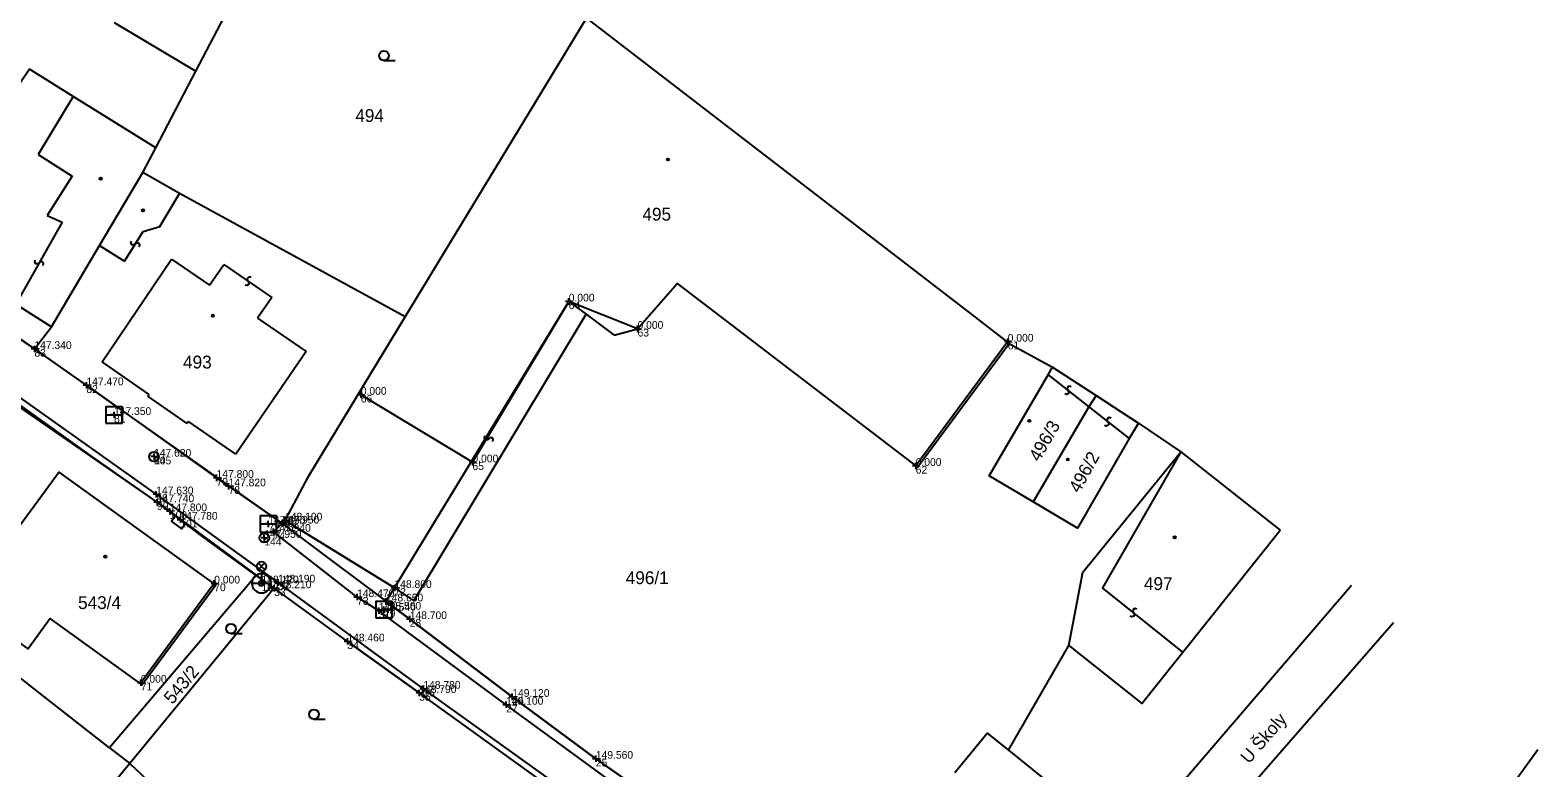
# Model space of a CAD drawing. Extents: x -748509 to -748117, y -967868 to -967533.
# Drawn here: x -748249.3 to -748131.8, y -967661.4 to -967603.9 of the extents above; entities that cross this region are included whole.
import ezdxf

# ---------------------------------------------------------------- set-up
doc = ezdxf.new("R2010")
doc.units = 0
for name, color, linetype in [('Body polohopisu', 7, 'Continuous'), ('Budovy', 7, 'Continuous'), ('Doplňkové značky', 7, 'Continuous'), ('KM', 7, 'Continuous'), ('Ploty_opěrné zdi', 7, 'Continuous'), ('Rozhraní ploch', 7, 'Continuous'), ('Vnitřní kresba', 7, 'Continuous'), ('Vstup na pozemek', 7, 'Continuous'), ('Výšky bodů', 7, 'Continuous'), ('Značky IS', 7, 'Continuous'), ('Čísla bodů', 7, 'Continuous')]:
    doc.layers.add(name, color=color, linetype=linetype)

msp = doc.modelspace()

# ---------------------------------------------------------------- linework, layer by layer
at = {"layer": 'Body polohopisu'}
for p, q in [((-748207.35, -967625.04), (-748207.6, -967625.04)), ((-748207.35, -967625.04), (-748207.35, -967624.79)), ((-748207.35, -967625.04), (-748207.1, -967625.04)), ((-748207.35, -967625.04), (-748207.35, -967625.29)), ((-748201.99, -967627.17), (-748202.24, -967627.17)), ((-748201.99, -967627.17), (-748201.99, -967626.92)), ((-748201.99, -967627.17), (-748201.74, -967627.17)), ((-748201.99, -967627.17), (-748201.99, -967627.42)), ((-748248.98, -967628.74), (-748249.23, -967628.74)), ((-748248.98, -967628.74), (-748248.98, -967628.49)), ((-748248.98, -967628.74), (-748248.73, -967628.74)), ((-748248.98, -967628.74), (-748248.98, -967628.99)), ((-748173.15, -967628.17), (-748173.4, -967628.17)), ((-748173.15, -967628.17), (-748173.15, -967627.92)), ((-748173.15, -967628.17), (-748172.9, -967628.17)), ((-748173.15, -967628.17), (-748173.15, -967628.42)), ((-748244.93, -967631.57), (-748245.18, -967631.57)), ((-748244.93, -967631.57), (-748244.93, -967631.32)), ((-748244.93, -967631.57), (-748244.68, -967631.57)), ((-748244.93, -967631.57), (-748244.93, -967631.82)), ((-748223.55, -967632.31), (-748223.8, -967632.31)), ((-748223.55, -967632.31), (-748223.55, -967632.06)), ((-748223.55, -967632.31), (-748223.3, -967632.31)), ((-748223.55, -967632.31), (-748223.55, -967632.56)), ((-748242.78, -967633.88), (-748243.03, -967633.88)), ((-748242.78, -967633.88), (-748242.78, -967633.63)), ((-748242.78, -967633.88), (-748242.53, -967633.88)), ((-748242.78, -967633.88), (-748242.78, -967634.13)), ((-748239.66, -967637.13), (-748239.66, -967636.88)), ((-748239.66, -967637.13), (-748239.66, -967636.88)), ((-748239.66, -967637.13), (-748239.91, -967637.13)), ((-748239.66, -967637.13), (-748239.91, -967637.13)), ((-748239.66, -967637.13), (-748239.41, -967637.13)), ((-748239.66, -967637.13), (-748239.66, -967637.38)), ((-748239.66, -967637.13), (-748239.41, -967637.13)), ((-748239.66, -967637.13), (-748239.66, -967637.38)), ((-748214.85, -967637.57), (-748215.1, -967637.57)), ((-748214.85, -967637.57), (-748214.85, -967637.32)), ((-748214.85, -967637.57), (-748214.6, -967637.57)), ((-748214.85, -967637.57), (-748214.85, -967637.82)), ((-748180.32, -967637.85), (-748180.57, -967637.85)), ((-748180.32, -967637.85), (-748180.32, -967637.6)), ((-748180.32, -967637.85), (-748180.07, -967637.85)), ((-748180.32, -967637.85), (-748180.32, -967638.1)), ((-748234.79, -967638.78), (-748235.04, -967638.78)), ((-748234.79, -967638.78), (-748234.79, -967638.53)), ((-748234.79, -967638.78), (-748234.54, -967638.78)), ((-748234.79, -967638.78), (-748234.79, -967639.03)), ((-748233.85, -967639.44), (-748233.85, -967639.19)), ((-748239.49, -967640.06), (-748239.74, -967640.06)), ((-748239.49, -967640.06), (-748239.49, -967639.81)), ((-748239.49, -967640.06), (-748239.24, -967640.06)), ((-748239.49, -967640.06), (-748239.49, -967640.31)), ((-748239.43, -967640.68), (-748239.43, -967640.43)), ((-748233.85, -967639.44), (-748234.1, -967639.44)), ((-748233.85, -967639.44), (-748233.6, -967639.44)), ((-748233.85, -967639.44), (-748233.85, -967639.69)), ((-748239.43, -967640.68), (-748239.68, -967640.68)), ((-748239.43, -967640.68), (-748239.18, -967640.68)), ((-748239.43, -967640.68), (-748239.43, -967640.93)), ((-748238.43, -967641.38), (-748238.68, -967641.38)), ((-748238.43, -967641.38), (-748238.43, -967641.13)), ((-748238.43, -967641.38), (-748238.18, -967641.38)), ((-748238.43, -967641.38), (-748238.43, -967641.63)), ((-748237.61, -967642.04), (-748237.86, -967642.04)), ((-748237.61, -967642.04), (-748237.61, -967641.79)), ((-748237.61, -967642.04), (-748237.36, -967642.04)), ((-748237.61, -967642.04), (-748237.61, -967642.29)), ((-748230.76, -967642.37), (-748231.01, -967642.37)), ((-748230.76, -967642.37), (-748230.76, -967642.12)), ((-748230.76, -967642.37), (-748230.51, -967642.37)), ((-748230.76, -967642.37), (-748230.76, -967642.62)), ((-748230.35, -967642.98), (-748230.35, -967642.73)), ((-748229.69, -967642.34), (-748229.94, -967642.34)), ((-748229.45, -967642.1), (-748229.7, -967642.1)), ((-748229.69, -967642.34), (-748229.69, -967642.09)), ((-748229.69, -967642.34), (-748229.44, -967642.34)), ((-748229.69, -967642.34), (-748229.69, -967642.59)), ((-748229.45, -967642.1), (-748229.45, -967641.85)), ((-748229.45, -967642.1), (-748229.2, -967642.1)), ((-748229.45, -967642.1), (-748229.45, -967642.35)), ((-748231.07, -967643.45), (-748231.32, -967643.45)), ((-748231.07, -967643.45), (-748231.07, -967643.2)), ((-748231.07, -967643.45), (-748230.82, -967643.45)), ((-748231.07, -967643.45), (-748231.07, -967643.7)), ((-748230.35, -967642.98), (-748230.6, -967642.98)), ((-748230.35, -967642.98), (-748230.1, -967642.98)), ((-748230.35, -967642.98), (-748230.35, -967643.23)), ((-748234.97, -967647.01), (-748235.22, -967647.01)), ((-748234.97, -967647.01), (-748234.97, -967646.76)), ((-748234.97, -967647.01), (-748234.72, -967647.01)), ((-748234.97, -967647.01), (-748234.97, -967647.26)), ((-748231.29, -967647), (-748231.54, -967647)), ((-748231.29, -967647), (-748231.29, -967646.75)), ((-748231.29, -967647), (-748231.04, -967647)), ((-748231.29, -967647), (-748231.29, -967647.25)), ((-748230.3, -967647.38), (-748230.55, -967647.38)), ((-748230.3, -967647.38), (-748230.3, -967647.13)), ((-748230.3, -967647.38), (-748230.05, -967647.38)), ((-748230.3, -967647.38), (-748230.3, -967647.63)), ((-748230, -967646.93), (-748230.25, -967646.93)), ((-748230, -967646.93), (-748230, -967646.68)), ((-748230, -967646.93), (-748229.75, -967646.93)), ((-748230, -967646.93), (-748230, -967647.18)), ((-748220.93, -967647.36), (-748221.18, -967647.36)), ((-748220.93, -967647.36), (-748220.93, -967647.11)), ((-748220.93, -967647.36), (-748220.68, -967647.36)), ((-748220.93, -967647.36), (-748220.93, -967647.61)), ((-748223.84, -967648.07), (-748224.09, -967648.07)), ((-748223.84, -967648.07), (-748223.84, -967647.82)), ((-748223.84, -967648.07), (-748223.59, -967648.07)), ((-748223.84, -967648.07), (-748223.84, -967648.32)), ((-748221.59, -967648.41), (-748221.84, -967648.41)), ((-748221.75, -967649.05), (-748221.75, -967648.8)), ((-748221.59, -967648.41), (-748221.59, -967648.16)), ((-748221.59, -967648.41), (-748221.34, -967648.41)), ((-748221.59, -967648.41), (-748221.59, -967648.66)), ((-748222.16, -967649.13), (-748222.41, -967649.13)), ((-748222.16, -967649.13), (-748222.16, -967648.88)), ((-748222.16, -967649.13), (-748221.91, -967649.13)), ((-748222.16, -967649.13), (-748222.16, -967649.38)), ((-748221.75, -967649.05), (-748222, -967649.05)), ((-748221.75, -967649.05), (-748221.5, -967649.05)), ((-748221.75, -967649.05), (-748221.75, -967649.3)), ((-748219.74, -967649.78), (-748219.99, -967649.78)), ((-748219.74, -967649.78), (-748219.74, -967649.53)), ((-748219.74, -967649.78), (-748219.49, -967649.78)), ((-748219.74, -967649.78), (-748219.74, -967650.03)), ((-748224.6, -967651.52), (-748224.85, -967651.52)), ((-748224.6, -967651.52), (-748224.6, -967651.27)), ((-748224.6, -967651.52), (-748224.35, -967651.52)), ((-748224.6, -967651.52), (-748224.6, -967651.77)), ((-748240.69, -967654.74), (-748240.69, -967654.49)), ((-748240.69, -967654.74), (-748240.94, -967654.74)), ((-748240.69, -967654.74), (-748240.44, -967654.74)), ((-748240.69, -967654.74), (-748240.69, -967654.99)), ((-748219, -967655.54), (-748219.25, -967655.54)), ((-748219, -967655.54), (-748219, -967655.29)), ((-748219, -967655.54), (-748218.75, -967655.54)), ((-748219, -967655.54), (-748219, -967655.79)), ((-748218.68, -967655.21), (-748218.93, -967655.21)), ((-748218.68, -967655.21), (-748218.68, -967654.96)), ((-748218.68, -967655.21), (-748218.43, -967655.21)), ((-748218.68, -967655.21), (-748218.68, -967655.46)), ((-748211.75, -967655.84), (-748212, -967655.84)), ((-748211.75, -967655.84), (-748211.75, -967655.59)), ((-748211.75, -967655.84), (-748211.5, -967655.84)), ((-748211.75, -967655.84), (-748211.75, -967656.09)), ((-748212.23, -967656.45), (-748212.48, -967656.45)), ((-748212.23, -967656.45), (-748212.23, -967656.2)), ((-748212.23, -967656.45), (-748211.98, -967656.45)), ((-748212.23, -967656.45), (-748212.23, -967656.7)), ((-748205.24, -967660.66), (-748205.24, -967660.41)), ((-748205.24, -967660.66), (-748205.49, -967660.66)), ((-748205.24, -967660.66), (-748204.99, -967660.66)), ((-748205.24, -967660.66), (-748205.24, -967660.91))]:
    msp.add_line(p, q, dxfattribs=at)
at = {"layer": 'Budovy'}
for points in [[(-748201.99, -967627.17), (-748207.35, -967625.04), (-748214.85, -967637.57), (-748223.55, -967632.31)], [(-748173.15, -967628.17), (-748180.32, -967637.85)], [(-748220.93, -967647.36), (-748229.45, -967642.1)], [(-748234.97, -967647.01), (-748240.69, -967654.74)]]:
    msp.add_lwpolyline(points, dxfattribs=at)
at = {"layer": 'Doplňkové značky'}
for p, q in [((-748231.55, -967645.94), (-748231.03, -967645.41)), ((-748231.02, -967645.94), (-748231.55, -967645.41)), ((-748231.29, -967646.05), (-748231.29, -967646.8))]:
    msp.add_line(p, q, dxfattribs=at)
for centre, radius in [((-748231.29, -967645.68), 0.375), ((-748231.29, -967647), 0.2)]:
    msp.add_circle(centre, radius, dxfattribs=at)
at = {"layer": 'KM'}
for p, q in [((-748236.4, -967607.09), (-748226.27, -967587.7)), ((-748220.09, -967626.24), (-748205.97, -967602.97)), ((-748242.78, -967603.32), (-748236.4, -967607.09)), ((-748221.75, -967606.28), (-748220.87, -967606.28)), ((-748239.53, -967613.07), (-748236.4, -967607.09)), ((-748240.54, -967615), (-748239.53, -967613.07)), ((-748259.38, -967621.54), (-748248.98, -967628.74)), ((-748248.98, -967628.74), (-748229.69, -967642.34)), ((-748173.05, -967628.31), (-748169.65, -967630.17)), ((-748169.65, -967630.17), (-748166.27, -967632.36)), ((-748166.27, -967632.36), (-748162.97, -967634.53)), ((-748162.97, -967634.53), (-748159.66, -967636.76)), ((-748159.66, -967636.76), (-748151.92, -967642.86)), ((-748229.69, -967642.34), (-748229.45, -967642.1)), ((-748231.71, -967646.39), (-748243.13, -967659.81)), ((-748230.3, -967647.38), (-748231.71, -967646.39)), ((-748230.3, -967647.38), (-748241.55, -967661.04)), ((-748163.76, -967667.39), (-748146.37, -967647.14)), ((-748233.67, -967650.91), (-748232.79, -967650.91)), ((-748173.09, -967660), (-748168.38, -967651.84)), ((-748227.2, -967657.58), (-748226.32, -967657.58)), ((-748243.13, -967659.81), (-748241.55, -967661.04)), ((-748159.06, -967697.45), (-748131.85, -967659.94)), ((-748241.55, -967661.04), (-748256.12, -967678.46)), ((-748241.55, -967661.04), (-748221.23, -967680.08))]:
    msp.add_line(p, q, dxfattribs=at)
for points in [[(-748205.97, -967602.97), (-748176.02, -967626), (-748173.05, -967628.31)], [(-748239.53, -967613.07), (-748245.95, -967609.07), (-748249.36, -967606.94), (-748251.89, -967610.64), (-748259.47, -967605.44), (-748265.77, -967614.58), (-748258.33, -967619.66), (-748259.38, -967621.54)], [(-748248.98, -967628.74), (-748247.66, -967627.02), (-748243.91, -967620.68), (-748240.54, -967615)], [(-748220.09, -967626.24), (-748237.67, -967616.64), (-748240.54, -967615)], [(-748231.71, -967646.39), (-748235.78, -967643.43), (-748239.43, -967640.68), (-748244.42, -967637.16), (-748269.93, -967618.95)], [(-748229.45, -967642.1), (-748220.93, -967647.36), (-748219.41, -967648.37), (-748206, -967626.04), (-748203.81, -967627.67), (-748201.99, -967627.17), (-748198.9, -967623.64), (-748196.5, -967625.48), (-748180.19, -967637.95), (-748173.05, -967628.31)], [(-748229.45, -967642.1), (-748227.6, -967638.63), (-748220.09, -967626.24)], [(-748171.16, -967640.65), (-748174.6, -967638.62), (-748170, -967630.75), (-748169.65, -967630.17)], [(-748166.27, -967632.36), (-748166.83, -967633.25), (-748171.16, -967640.65)], [(-748162.97, -967634.53), (-748163.69, -967635.72), (-748167.71, -967642.69), (-748171.16, -967640.65)], [(-748168.38, -967651.84), (-748167.3, -967646.13), (-748159.66, -967636.76)], [(-748254.51, -967648.43), (-748247.07, -967638.35), (-748234.85, -967647.14), (-748240.58, -967654.9), (-748247.76, -967649.74), (-748249.46, -967652.1), (-748254.51, -967648.43)], [(-748229.69, -967642.34), (-748219.74, -967649.78), (-748211.75, -967655.84), (-748205.24, -967660.66), (-748198.43, -967665.43), (-748187.84, -967672.99), (-748185.42, -967672.41), (-748179.89, -967671.41), (-748179.35, -967670.75)], [(-748168.38, -967651.84), (-748162.71, -967656.37), (-748159.5, -967652.36), (-748151.92, -967642.86)], [(-748208.42, -967663.17), (-748219, -967655.54), (-748224.6, -967651.52), (-748230.3, -967647.38)], [(-748243.13, -967659.81), (-748248.64, -967655.5), (-748256.43, -967649.41)], [(-748143.1, -967650.08), (-748174.48, -967686.04), (-748161.31, -967696.92), (-748159.06, -967697.45)], [(-748177.27, -967661.74), (-748174.74, -967658.67), (-748173.09, -967660)], [(-748173.09, -967660), (-748168.63, -967663.6), (-748163.76, -967667.39)]]:
    msp.add_lwpolyline(points, dxfattribs=at)
for centre, radius in [((-748221.75, -967605.9), 0.375), ((-748199.62, -967613.98), 0.0875), ((-748243.82, -967615.47), 0.0875), ((-748240.53, -967617.94), 0.0875), ((-748235.08, -967626.15), 0.0875), ((-748171.46, -967634.34), 0.0875), ((-748168.47, -967637.35), 0.0875), ((-748160.14, -967643.42), 0.0875), ((-748243.45, -967644.92), 0.0875), ((-748233.67, -967650.53), 0.375), ((-748227.2, -967657.2), 0.375)]:
    msp.add_circle(centre, radius, dxfattribs=at)
at = {"layer": 'Ploty_opěrné zdi'}
for points in [[(-748239.43, -967640.68), (-748254.08, -967630.54), (-748266.63, -967622)], [(-748248.98, -967628.74), (-748255.39, -967624.4)], [(-748244.93, -967631.57), (-748234.79, -967638.78)], [(-748233.85, -967639.44), (-748229.69, -967642.34)], [(-748224.6, -967651.52), (-748230.3, -967647.38), (-748238.43, -967641.38)], [(-748219.74, -967649.78), (-748221.59, -967648.41), (-748220.93, -967647.36)], [(-748211.75, -967655.84), (-748219.74, -967649.78)], [(-748199.23, -967672.68), (-748197.92, -967671.02), (-748208.42, -967663.17), (-748219, -967655.54)], [(-748188.75, -967672.34), (-748198.43, -967665.43), (-748205.24, -967660.66), (-748211.75, -967655.84)]]:
    msp.add_lwpolyline(points, dxfattribs=at)
at = {"layer": 'Rozhraní ploch'}
for points in [[(-748199.23, -967672.68), (-748197.54, -967670.59), (-748208.01, -967662.84), (-748218.68, -967655.21), (-748230, -967646.93), (-748239.49, -967640.06), (-748253.68, -967630.01), (-748266.22, -967621.62), (-748268.01, -967621.08)], [(-748188.75, -967672.34), (-748189.47, -967672.82), (-748198.76, -967666.3), (-748212.23, -967656.45), (-748222.16, -967649.13), (-748223.84, -967648.07), (-748230.35, -967642.98), (-748229.69, -967642.34)]]:
    msp.add_lwpolyline(points, dxfattribs=at)
at = {"layer": 'Vnitřní kresba'}
for p, q in [((-748245.95, -967609.07), (-748248.69, -967613.6)), ((-748248.69, -967613.6), (-748246.05, -967615.27)), ((-748246.05, -967615.27), (-748248, -967618.34)), ((-748239.2, -967619.2), (-748237.67, -967616.64)), ((-748246.83, -967618.87), (-748250.42, -967625.26)), ((-748248, -967618.34), (-748246.83, -967618.87)), ((-748240.5, -967619.59), (-748239.2, -967619.2)), ((-748241.97, -967621.9), (-748240.5, -967619.59)), ((-748243.91, -967620.68), (-748241.97, -967621.9)), ((-748243.71, -967629.74), (-748238.3, -967621.75)), ((-748238.3, -967621.75), (-748235.34, -967623.78)), ((-748235.34, -967623.78), (-748234.23, -967622.16)), ((-748234.23, -967622.16), (-748230.48, -967624.73)), ((-748250.42, -967625.26), (-748247.66, -967627.02)), ((-748230.48, -967624.73), (-748231.6, -967626.35)), ((-748220.93, -967647.36), (-748207.35, -967625.04)), ((-748207.35, -967625.04), (-748206, -967626.04)), ((-748231.6, -967626.35), (-748227.81, -967628.95)), ((-748240.04, -967632.28), (-748243.71, -967629.74)), ((-748227.81, -967628.95), (-748233.3, -967636.94)), ((-748170, -967630.75), (-748166.83, -967633.25)), ((-748240.14, -967632.42), (-748240.04, -967632.28)), ((-748237.08, -967634.54), (-748240.14, -967632.42)), ((-748166.83, -967633.25), (-748163.69, -967635.72)), ((-748236.98, -967634.39), (-748237.08, -967634.54)), ((-748233.3, -967636.94), (-748236.98, -967634.39)), ((-748159.66, -967636.76), (-748165.78, -967647.34)), ((-748159.5, -967652.36), (-748165.78, -967647.34))]:
    msp.add_line(p, q, dxfattribs=at)
for points in [[(-748240.82, -967620.79), (-748240.78, -967620.63), (-748240.88, -967620.5), (-748241.03, -967620.49), (-748241.23, -967620.64), (-748241.38, -967620.62), (-748241.47, -967620.48), (-748241.42, -967620.34)], [(-748248.3, -967622.25), (-748248.27, -967622.09), (-748248.37, -967621.96), (-748248.52, -967621.96), (-748248.72, -967622.12), (-748248.87, -967622.11), (-748248.96, -967621.98), (-748248.93, -967621.83)], [(-748232.1, -967623.17), (-748232.25, -967623.12), (-748232.39, -967623.22), (-748232.41, -967623.37), (-748232.26, -967623.57), (-748232.29, -967623.72), (-748232.43, -967623.8), (-748232.56, -967623.76)], [(-748168.21, -967631.69), (-748168.36, -967631.63), (-748168.5, -967631.72), (-748168.53, -967631.87), (-748168.39, -967632.08), (-748168.43, -967632.23), (-748168.58, -967632.3), (-748168.71, -967632.24)], [(-748165.1, -967634.13), (-748165.25, -967634.08), (-748165.39, -967634.17), (-748165.42, -967634.31), (-748165.28, -967634.53), (-748165.32, -967634.68), (-748165.47, -967634.75), (-748165.6, -967634.69)], [(-748213.26, -967635.95), (-748213.23, -967635.79), (-748213.33, -967635.66), (-748213.48, -967635.65), (-748213.68, -967635.81), (-748213.83, -967635.79), (-748213.92, -967635.66), (-748213.88, -967635.52)], [(-748163.09, -967649.01), (-748163.24, -967648.95), (-748163.39, -967649.04), (-748163.41, -967649.19), (-748163.28, -967649.4), (-748163.32, -967649.55), (-748163.47, -967649.62), (-748163.6, -967649.56)]]:
    msp.add_lwpolyline(points, dxfattribs=at)
at = {"layer": 'Vstup na pozemek'}
for points in [[(-748244.93, -967631.57), (-748248.98, -967628.74)], [(-748233.85, -967639.44), (-748234.79, -967638.78)], [(-748239.43, -967640.68), (-748238.43, -967641.38)], [(-748224.6, -967651.52), (-748219, -967655.54)]]:
    msp.add_lwpolyline(points, dxfattribs=at)
at = {"layer": 'Značky IS'}
for p, q in [((-748243.41, -967633.88), (-748242.16, -967633.88)), ((-748231.39, -967642.37), (-748230.14, -967642.37)), ((-748230.54, -967647), (-748232.04, -967647)), ((-748222.38, -967649.05), (-748221.13, -967649.05))]:
    msp.add_line(p, q, dxfattribs=at)
for points in [[(-748243.41, -967634.51), (-748242.15, -967634.51), (-748242.15, -967633.25), (-748243.41, -967633.25)], [(-748237.21, -967642.34), (-748237.5, -967642.74), (-748238.31, -967642.15), (-748238.01, -967641.74)], [(-748231.39, -967643), (-748230.13, -967643), (-748230.13, -967641.74), (-748231.39, -967641.74)], [(-748222.38, -967649.68), (-748221.12, -967649.68), (-748221.12, -967648.42), (-748222.38, -967648.42)]]:
    msp.add_lwpolyline(points, close=True, dxfattribs=at)
for centre in [(-748239.66, -967637.13), (-748239.66, -967637.13), (-748231.07, -967643.45)]:
    msp.add_circle(centre, 0.375, dxfattribs=at)
for start, end in [(0, 180), (180, 0)]:
    msp.add_arc((-748231.29, -967647), 0.747, start, end, dxfattribs=at)

# ---------------------------------------------------------------- texts
at = {"layer": 'KM'}
for s, p in [('494', (-748223.98, -967611.06)), ('495', (-748201.61, -967618.74)), ('493', (-748237.4, -967630.26)), ('496/1', (-748202.91, -967647.06)), ('497', (-748162.54, -967647.52)), ('543/4', (-748245.58, -967649))]:
    msp.add_text(s, height=1, dxfattribs=at).set_placement(p)
for s, rotation, p in [('496/3', 60, (-748170.7, -967637.59)), ('496/2', 61, (-748167.58, -967640.03)), ('543/2', 50, (-748238.23, -967656.48)), ('U Školy', 49, (-748154.36, -967661.11))]:
    msp.add_text(s, height=1, rotation=rotation, dxfattribs=at).set_placement(p)
at = {"layer": 'Výšky bodů'}
for s, p in [('0.000', (-748207.35, -967625.04)), ('0.000', (-748201.99, -967627.17)), ('0.000', (-748173.15, -967628.17)), ('147.340', (-748248.98, -967628.74)), ('147.470', (-748244.93, -967631.57)), ('0.000', (-748223.55, -967632.31)), ('147.350', (-748242.78, -967633.88)), ('147.630', (-748239.66, -967637.13)), ('147.620', (-748239.66, -967637.13)), ('0.000', (-748214.85, -967637.57)), ('147.800', (-748234.79, -967638.78)), ('0.000', (-748180.32, -967637.85)), ('147.820', (-748233.85, -967639.44)), ('147.630', (-748239.49, -967640.06)), ('147.740', (-748239.43, -967640.68)), ('147.800', (-748238.43, -967641.38)), ('147.780', (-748237.61, -967642.04)), ('147.950', (-748229.69, -967642.34)), ('148.100', (-748229.45, -967642.1)), ('147.950', (-748231.07, -967643.45)), ('147.890', (-748230.76, -967642.37)), ('147.940', (-748230.35, -967642.98)), ('0.000', (-748234.97, -967647.01)), ('148.120', (-748231.29, -967647)), ('148.190', (-748230, -967646.93)), ('148.210', (-748230.3, -967647.38)), ('148.470', (-748223.84, -967648.07)), ('148.800', (-748220.93, -967647.36)), ('148.540', (-748222.16, -967649.13)), ('148.560', (-748221.75, -967649.05)), ('148.650', (-748221.59, -967648.41)), ('148.700', (-748219.74, -967649.78)), ('148.460', (-748224.6, -967651.52)), ('0.000', (-748240.69, -967654.74)), ('148.780', (-748218.68, -967655.21)), ('148.790', (-748219, -967655.54)), ('149.100', (-748212.23, -967656.45)), ('149.120', (-748211.75, -967655.84)), ('149.560', (-748205.24, -967660.66))]:
    msp.add_text(s, height=0.6, dxfattribs=at).set_placement(p)
at = {"layer": 'Čísla bodů'}
for s, p in [('64', (-748207.35, -967625.64)), ('63', (-748201.99, -967627.77)), ('83', (-748248.98, -967629.34)), ('61', (-748173.15, -967628.77)), ('82', (-748244.93, -967632.17)), ('66', (-748223.55, -967632.91)), ('81', (-748242.78, -967634.48)), ('80', (-748239.66, -967637.73)), ('145', (-748239.66, -967637.73)), ('65', (-748214.85, -967638.17)), ('62', (-748180.32, -967638.45)), ('79', (-748234.79, -967639.38)), ('98', (-748239.49, -967640.66)), ('78', (-748233.85, -967640.04)), ('99', (-748239.43, -967641.28)), ('100', (-748238.43, -967641.98)), ('101', (-748237.61, -967642.64)), ('77', (-748230.76, -967642.97)), ('76', (-748229.69, -967642.94)), ('75', (-748229.45, -967642.7)), ('144', (-748231.07, -967644.05)), ('74', (-748230.35, -967643.58)), ('70', (-748234.97, -967647.61)), ('102', (-748231.29, -967647.6)), ('33', (-748230.3, -967647.98)), ('32', (-748230, -967647.53)), ('72', (-748220.93, -967647.96)), ('73', (-748223.84, -967648.67)), ('30', (-748221.59, -967649.01)), ('31', (-748222.16, -967649.73)), ('29', (-748221.75, -967649.65)), ('28', (-748219.74, -967650.38)), ('34', (-748224.6, -967652.12)), ('71', (-748240.69, -967655.34)), ('35', (-748219, -967656.14)), ('36', (-748218.68, -967655.81)), ('26', (-748211.75, -967656.44)), ('27', (-748212.23, -967657.05)), ('25', (-748205.24, -967661.26))]:
    msp.add_text(s, height=0.6, dxfattribs=at).set_placement(p)

doc.saveas('drawing.dxf')
